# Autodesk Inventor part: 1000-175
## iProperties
Created: 2007-03
Part Number: 1000-175
Document SubType Name: Modeling
Designer: Andy Moles
Material: Steel
Mass: 20.2349 g
Surface Area: 20.3118 cm^2
Volume: 2.57769 cm^3
Density: 7.85 g/cm^3
Author: Andy Moles
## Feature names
1. Base1
